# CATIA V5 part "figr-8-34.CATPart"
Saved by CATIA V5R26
Part number: Part1
Bounding box of the stored display mesh (mm): x -75 to 75, y -75 to 75, z 0 to 20
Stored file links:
  D:\_Deepak\CATIA\CATIA V5-6R2016_Deepak\Resources\Part files\Partfiles\c08_catia_v5_6r2016_prt\figr-8-34.CATPart
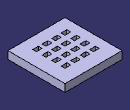
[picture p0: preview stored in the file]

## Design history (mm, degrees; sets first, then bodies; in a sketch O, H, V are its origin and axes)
Body1 (main body)
  Sketch1 on xy-plane, origin (0, 0, 0), H (1, 0, 0), V (0, 1, 0)
    line L1 (-75, 75) -> (75, 75)
    line L2 (75, 75) -> (75, -75)
    line L3 (75, -75) -> (-75, -75)
    line L4 (-75, -75) -> (-75, 75)
    axis line L5 (75, -75) -> (-75, 75)
    length L3 = 150
    length L2 = 150
    horizontal: L1 H, L3 H
    vertical: L2 V, L4 V
    midpoint: O L5
  Pad1: profile Sketch1, direction (0, 0, 1), length 20
  Sketch2 on face of Pad1, origin (0, 0, 20), H (1, 0, 0), V (0, 1, 0)
    line L1 (25, 40) -> (40, 40)
    line L2 (40, 40) -> (40, 30)
    line L3 (40, 30) -> (25, 30)
    line L4 (25, 30) -> (25, 40)
    reference projected line E1 (75, -75) -> (75, 75) from edge [face of Pad1 | face of Pad1]
    reference projected line E2 (75, 75) -> (-75, 75) from edge [face of Pad1 | face of Pad1]
    length L3 = 15
    length L4 = 10
    distance L2 E1 = 35
    distance L1 E2 = 35
    horizontal: L1 H, L3 H
    vertical: L2 V, L4 V
  Pocket1: profile Sketch2, direction (0, 0, -1), through (limit type 3)
  RectPattern1: of Pocket1, direction 1 instances 4, spacing 25, along end face of Pad1 reversed, direction 2 instances 4, spacing 25, along end face of Pad1 reversed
